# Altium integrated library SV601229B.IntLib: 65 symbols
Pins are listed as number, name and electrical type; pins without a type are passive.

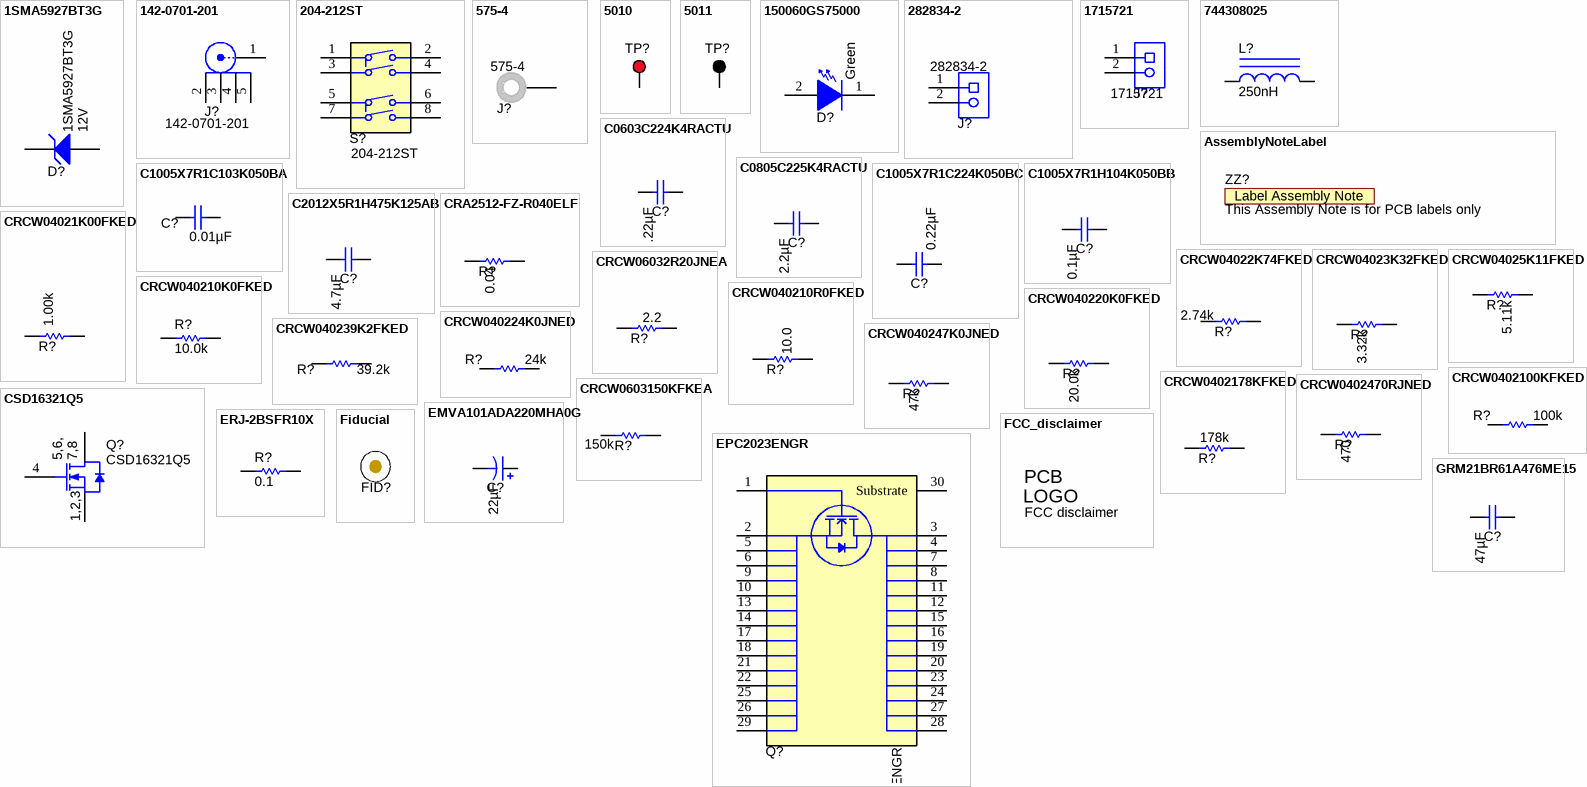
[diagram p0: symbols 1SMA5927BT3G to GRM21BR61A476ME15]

## 1SMA5927BT3G
designator D?  value 12V
Diode, Zener, 12 V, 1.5 W, SMA; Manufacturer: ON Semiconductor; SymbolCreator: a0412235; U/M: EA; Power_W: 1.5; Vz_V: 12; Value1: 1.5W; RJA_CperW: 250
signal-integrity model Diode
footprint SMA
pins: 1 K, 2 A

## 142-0701-201
designator J?
Connector, TH, SMA; Manufacturer: Emerson Network Power; SymbolCreator: X0208326; U/M: EA
footprint Johnson_142-0701-20x
pins: 1, 2, 3, 4, 5

## 204-212ST
designator S?
Switch, DPST, 2 Pos, 0.1 A, 50 VDC, SMD; Manufacturer: CTS Electrocomponents; SymbolCreator: Altium; VDC_V: 50; SwitchFunction: Off-On; PositionCount: 2; CurrentRating_mA: 100
footprint SW_204-212
pins: 1, 2, 3, 4, 5, 6, 7, 8

## 575-4
designator J?
Standard Banana Jack, Uninsulated, 5.5mm; Manufacturer: Keystone; CompType: Connector; U/M: EA
footprint Keystone_575-4
pins: 1

## 5010
designator TP?  (value not drawn)
Test Point, Multipurpose, Red, TH; Manufacturer: Keystone; CompType: Test Point Loop; U/M: EA
footprint Keystone5010
pins: 1

## 5011
designator TP?  (value not drawn)
Test Point, Multipurpose, Black, TH; Manufacturer: Keystone; CompType: Test Point Loop; U/M: EA
footprint Keystone5011
pins: 1

## 150060GS75000
designator D?  value Green  (hidden comment: 150060GS75000)
LED, Green, SMD; Manufacturer: Wurth Elektronik eiSos; Type: InGaN; Vf_V: 3.2; Value2: 3.2V; Io_A: 0.02; Tjmax_C: 85; Value1: W; Angle: 140; U/M: EA
signal-integrity model Diode
footprint WL-SMCW_GREEN
pins: 1 K, 2 A

## 282834-2
designator J?
Terminal Block, 2x1, 2.54mm, TH; Manufacturer: TE Connectivity; SymbolCreator: a0412235; U/M: EA
footprint TEC_282834-2
pins: 1, 2

## 1715721
designator J?
Terminal Block, 5.08 mm, 2x1, TH; Manufacturer: Phoenix Contact; SymbolCreator: a0412235; Pitch_mm: 5.08; Gender: Female; Row_Count: 1; ContactFinish: Tin; Current_A: 17.5; Voltage_V: 400; Cert_CSA: Y; Cert_CULUS: N
footprint PhoenixContact_1715721
pins: 1, 2

## 744308025
designator L?  ValueDisplayed: 250nH  (hidden comment: 744308025)
Inductor, Shielded Drum Core, Ferrite, 250 nH, 27 A, 0.00037 ohm, SMD; Manufacturer: Wurth Elektronik; Value: 250nH; Ind_H: 250.0E-9; Imax_A: 27; Irms: 27A @ 50C rise; Isat: 44A @ 20% inductance drop; Value2: 27A
signal-integrity model Inductor
simulation model Inductor
footprint WE-HCM_1070
pins: 1, 2

## AssemblyNoteLabel
designator ZZ?, comment This Assembly Note is for PCB labels only  (no BOM)
SymbolCreator: a0412235
footprint AssemblyNoteLabel

## C0603C224K4RACTU
designator C?  ValueDisplayed: 0.22µF  (hidden comment: C0603C224K4RACTU)
CAP, CERM, 0.22 µF, 16 V, +/- 10%, X7R, 0603; Manufacturer: Kemet; Polarized: N; CompType: Capacitor; Value: 0.22uF; U/M: EA; Cap_F: 0.00000022; Tolerance_%: 10; Value1: Unknown; VDC_V: 16; Value2: 16V; TaMin_C: -55; TaMax_C: 125; Cap_Case: 0603
signal-integrity model Cap
simulation model Cap
footprint 0603
footprint 0603M
footprint 0603L
footprint 0603_HV
footprint 0603S
pins: 1, 2

## C0805C225K4RACTU
designator C?  ValueDisplayed: 2.2µF  (hidden comment: C0805C225K4RACTU)
CAP, CERM, 2.2 µF, 16 V, +/- 10%, X7R, 0805; Manufacturer: Kemet; Polarized: N; CompType: Capacitor; Value: 2.2uF; U/M: EA; Cap_F: 0.0000022; Tolerance_%: 10; ESR_ohm: 0.008; Value1: 0.008 ohm; VDC_V: 16; Value2: 16V; IRMS_A: 15.55; TaMin_C: -55; TaMax_C: 125; Cap_Case: 0805
signal-integrity model Cap
simulation model Cap
footprint 0805_HV
footprint 0805
footprint 0805M
footprint 0805L
pins: 1, 2

## C1005X7R1C103K050BA
designator C?  ValueDisplayed: 0.01µF  (hidden comment: C1005X7R1C103K050BA)
CAP, CERM, 0.01 µF, 16 V, +/- 10%, X7R, 0402; Manufacturer: TDK; Polarized: N; CompType: Capacitor; Value: 0.01uF; U/M: EA; Cap_F: 0.00000001; Tolerance_%: 10; ESR_ohm: 0.0623; Value1: 0.0623 ohm; VDC_V: 16; Value2: 16V; TaMin_C: -55; TaMax_C: 125; Cap_Case: 0402; AEC Category: Q200
signal-integrity model Cap
simulation model Cap
footprint 0402
footprint 0402M
footprint 0402L
footprint 0402S
pins: 1, 2

## C1005X7R1C224K050BC
designator C?  ValueDisplayed: 0.22µF  (hidden comment: C1005X7R1C224K050BC)
CAP, CERM, 0.22 µF, 16 V, +/- 10%, X7R, 0402; Manufacturer: TDK; Polarized: N; CompType: Capacitor; Value: 0.22uF; U/M: EA; Cap_F: 0.00000022; Tolerance_%: 10; Value1: Unknown; VDC_V: 16; Value2: 16V; TaMin_C: -55; TaMax_C: 125; Cap_Case: 0402
signal-integrity model Cap
simulation model Cap
footprint 0402
footprint 0402M
footprint 0402L
footprint 0402S
pins: 1, 2

## C1005X7R1H104K050BB
designator C?  ValueDisplayed: 0.1µF  (hidden comment: C1005X7R1H104K050BB)
CAP, CERM, 0.1 µF, 50 V, +/- 10%, X7R, 0402; Manufacturer: TDK; Polarized: N; CompType: Capacitor; Value: 0.1uF; U/M: EA; Cap_F: 0.0000001; Tolerance_%: 10; ESR_ohm: 0.039064; Value1: 0.039064 ohm; VDC_V: 50; Value2: 50V; IRMS_A: 0.814669; TaMin_C: -55; TaMax_C: 125; Cap_Case: 0402; AEC Category: Q200
signal-integrity model Cap
simulation model Cap
footprint 0402
footprint 0402M
footprint 0402L
footprint 0402S
pins: 1, 2

## C2012X5R1H475K125AB
designator C?  ValueDisplayed: 4.7µF  (hidden comment: C2012X5R1H475K125AB)
CAP, CERM, 4.7uF, 50V, +/-10%, X5R, 0805; Manufacturer: TDK; Polarized: N; CompType: Capacitor; U/M: EA; Cap_F: 0.0000047; Tolerance_%: 10; Value1: Unknown; VDC_V: 50; TaMin_C: -55; TaMax_C: 85; Cap_Case: 0805
signal-integrity model Cap
simulation model Cap
footprint 0805_HV
footprint 0805
footprint 0805M
footprint 0805L
pins: 1, 2

## CRA2512-FZ-R040ELF
designator R?  ValueDisplayed: 0.04  (hidden comment: CRA2512-FZ-R040ELF)
RES, 0.04, 1%, 3 W, 2512; Manufacturer: Bourns; CompType: Resistor; Value: 0.04; Value_Code: R040; Tolerance_%: 1; Power_W: 3; Value2: 3W; VDC_V: 0; TempCo: 75 ppm/C; U/M: EA
signal-integrity model Resistor
simulation model Resistor
footprint 2512
footprint 2512M
footprint 2512L
pins: 1, 2

## CRCW04021K00FKED
designator R?  ValueDisplayed: 1.00k  (hidden comment: CRCW04021K00FKED)
RES, 1.00 k, 1%, 0.063 W, 0402; Manufacturer: Vishay-Dale; CompType: Resistor; Value: 1.00k; Res_ohm: 1000; Value_Code: 1k00; Tolerance_%: 1; Power_W: 0.063; Value2: 0.063W; VDC_V: 50; TempCo: 100 ppm/C; EIA_Code: E96; U/M: EA; AEC Category: Q200
signal-integrity model Resistor
simulation model Resistor
footprint 0402
footprint 0402M
footprint 0402L
footprint 0402S
pins: 1, 2

## CRCW04022K74FKED
designator R?  ValueDisplayed: 2.74k  (hidden comment: CRCW04022K74FKED)
RES, 2.74 k, 1%, 0.063 W, 0402; Manufacturer: Vishay-Dale; CompType: Resistor; Value: 2.74k; Res_ohm: 2740; Value_Code: 2k74; Tolerance_%: 1; Power_W: 0.063; Value2: 0.063W; VDC_V: 50; TempCo: 100 ppm/C; EIA_Code: E96; U/M: EA
signal-integrity model Resistor
simulation model Resistor
footprint 0402
footprint 0402M
footprint 0402L
footprint 0402S
pins: 1, 2

## CRCW04023K32FKED
designator R?  ValueDisplayed: 3.32k  (hidden comment: CRCW04023K32FKED)
RES, 3.32 k, 1%, 0.063 W, 0402; Manufacturer: Vishay-Dale; CompType: Resistor; Value: 3.32k; Res_ohm: 3320; Value_Code: 3k32; Tolerance_%: 1; Power_W: 0.063; Value2: 0.063W; VDC_V: 50; TempCo: 100 ppm/C; EIA_Code: E96; U/M: EA
signal-integrity model Resistor
simulation model Resistor
footprint 0402
footprint 0402M
footprint 0402L
footprint 0402S
pins: 1, 2

## CRCW04025K11FKED
designator R?  ValueDisplayed: 5.11k  (hidden comment: CRCW04025K11FKED)
RES, 5.11 k, 1%, 0.063 W, 0402; Manufacturer: Vishay-Dale; CompType: Resistor; Value: 5.11k; Res_ohm: 5110; Value_Code: 5k11; Tolerance_%: 1; Power_W: 0.063; Value2: 0.063W; VDC_V: 50; TempCo: 100 ppm/C; EIA_Code: E96; U/M: EA
signal-integrity model Resistor
simulation model Resistor
footprint 0402
footprint 0402M
footprint 0402L
footprint 0402S
pins: 1, 2

## CRCW06032R20JNEA
designator R?  ValueDisplayed: 2.2  (hidden comment: CRCW06032R20JNEA)
RES, 2.2, 5%, 0.1 W, 0603; Manufacturer: Vishay-Dale; CompType: Resistor; Value: 2.2; Value_Code: 2R20; Tolerance_%: 5; Power_W: 0.1; Value2: 0.1W; VDC_V: 75; TempCo: 200 ppm/C; EIA_Code: E24; U/M: EA
signal-integrity model Resistor
simulation model Resistor
footprint 0603
footprint 0603M
footprint 0603L
footprint 0603_HV
footprint 0603S
pins: 1, 2

## CRCW040210K0FKED
designator R?  ValueDisplayed: 10.0k  (hidden comment: CRCW040210K0FKED)
RES, 10.0 k, 1%, 0.063 W, 0402; Manufacturer: Vishay-Dale; CompType: Resistor; Value: 10.0k; Res_ohm: 10000; Value_Code: 10k0; Tolerance_%: 1; Power_W: 0.063; Value2: 0.063W; VDC_V: 50; TempCo: 100 ppm/C; EIA_Code: E96; U/M: EA
signal-integrity model Resistor
simulation model Resistor
footprint 0402
footprint 0402M
footprint 0402L
footprint 0402S
pins: 1, 2

## CRCW040210R0FKED
designator R?  ValueDisplayed: 10.0  (hidden comment: CRCW040210R0FKED)
RES, 10.0, 1%, 0.063 W, 0402; Manufacturer: Vishay-Dale; CompType: Resistor; Value: 10.0; Res_ohm: 10; Value_Code: 10R0; Tolerance_%: 1; Power_W: 0.063; Value2: 0.063W; VDC_V: 50; TempCo: 100 ppm/C; EIA_Code: E96; U/M: EA
signal-integrity model Resistor
simulation model Resistor
footprint 0402
footprint 0402M
footprint 0402L
footprint 0402S
pins: 1, 2

## CRCW040220K0FKED
designator R?  ValueDisplayed: 20.0k  (hidden comment: CRCW040220K0FKED)
RES, 20.0 k, 1%, 0.063 W, 0402; Manufacturer: Vishay-Dale; CompType: Resistor; Value: 20.0k; Res_ohm: 20000; Value_Code: 20k0; Tolerance_%: 1; Power_W: 0.063; Value2: 0.063W; VDC_V: 50; TempCo: 100 ppm/C; EIA_Code: E96; U/M: EA
signal-integrity model Resistor
simulation model Resistor
footprint 0402
footprint 0402M
footprint 0402L
footprint 0402S
pins: 1, 2

## CRCW040224K0JNED
designator R?  ValueDisplayed: 24k  (hidden comment: CRCW040224K0JNED)
RES, 24 k, 5%, 0.063 W, 0402; Manufacturer: Vishay-Dale; CompType: Resistor; Value: 24k; Res_ohm: 24000; Value_Code: 24k0; Tolerance_%: 5; Power_W: 0.063; Value2: 0.063W; VDC_V: 50; TempCo: 200 ppm/C; EIA_Code: E24; U/M: EA
signal-integrity model Resistor
simulation model Resistor
footprint 0402
footprint 0402M
footprint 0402L
footprint 0402S
pins: 1, 2

## CRCW040239K2FKED
designator R?  ValueDisplayed: 39.2k  (hidden comment: CRCW040239K2FKED)
RES, 39.2 k, 1%, 0.063 W, 0402; Manufacturer: Vishay-Dale; CompType: Resistor; Value: 39.2k; Res_ohm: 39200; Value_Code: 39k2; Tolerance_%: 1; Power_W: 0.063; Value2: 0.063W; VDC_V: 50; TempCo: 100 ppm/C; EIA_Code: E96; U/M: EA
signal-integrity model Resistor
simulation model Resistor
footprint 0402
footprint 0402M
footprint 0402L
footprint 0402S
pins: 1, 2

## CRCW040247K0JNED
designator R?  ValueDisplayed: 47k  (hidden comment: CRCW040247K0JNED)
RES, 47 k, 5%, 0.063 W, 0402; Manufacturer: Vishay-Dale; CompType: Resistor; Value: 47k; Res_ohm: 47000; Value_Code: 47k0; Tolerance_%: 5; Power_W: 0.063; Value2: 0.063W; VDC_V: 50; TempCo: 200 ppm/C; EIA_Code: E24; U/M: EA
signal-integrity model Resistor
simulation model Resistor
footprint 0402
footprint 0402M
footprint 0402L
footprint 0402S
pins: 1, 2

## CRCW0402100KFKED
designator R?  ValueDisplayed: 100k  (hidden comment: CRCW0402100KFKED)
RES, 100 k, 1%, 0.063 W, 0402; Manufacturer: Vishay-Dale; CompType: Resistor; Value: 100k; Res_ohm: 100000; Tolerance_%: 1; Power_W: 0.063; Value2: 0.063W; VDC_V: 50; TempCo: 100 ppm/C; EIA_Code: E96; U/M: EA
signal-integrity model Resistor
simulation model Resistor
footprint 0402
footprint 0402M
footprint 0402L
footprint 0402S
pins: 1, 2

## CRCW0402178KFKED
designator R?  ValueDisplayed: 178k  (hidden comment: CRCW0402178KFKED)
RES, 178 k, 1%, 0.063 W, 0402; Manufacturer: Vishay-Dale; CompType: Resistor; Value: 178k; Res_ohm: 178000; Tolerance_%: 1; Power_W: 0.063; Value2: 0.063W; VDC_V: 50; TempCo: 100 ppm/C; EIA_Code: E96; U/M: EA
signal-integrity model Resistor
simulation model Resistor
footprint 0402
footprint 0402M
footprint 0402L
footprint 0402S
pins: 1, 2

## CRCW0402470RJNED
designator R?  ValueDisplayed: 470  (hidden comment: CRCW0402470RJNED)
RES, 470, 5%, 0.063 W, 0402; Manufacturer: Vishay-Dale; CompType: Resistor; Value: 470; Value_Code: 470R; Tolerance_%: 5; Power_W: 0.063; Value2: 0.063W; VDC_V: 50; TempCo: 200 ppm/C; EIA_Code: E24; U/M: EA
signal-integrity model Resistor
simulation model Resistor
footprint 0402
footprint 0402M
footprint 0402L
footprint 0402S
pins: 1, 2

## CRCW0603150KFKEA
designator R?  ValueDisplayed: 150k  (hidden comment: CRCW0603150KFKEA)
RES, 150 k, 1%, 0.1 W, 0603; Manufacturer: Vishay-Dale; CompType: Resistor; Value: 150k; Res_ohm: 150000; Tolerance_%: 1; Power_W: 0.1; Value2: 0.1W; VDC_V: 75; TempCo: 100 ppm/C; EIA_Code: E96; U/M: EA
signal-integrity model Resistor
simulation model Resistor
footprint 0603
footprint 0603M
footprint 0603L
footprint 0603_HV
footprint 0603S
pins: 1, 2

## CSD16321Q5
designator Q?
MOSFET, N-CH, 25 V, 100 A, SON 5x6mm; Manufacturer: Texas Instruments; Alternate Manufacturer: None; U/M: EA; ChType: N; Value: 25V; VdsMax_V: 25; Value1: 0.0021 ohm; Rdson45_ohm: 0.0021; Value2: 14 nC; QgTyp_nC: 14; Vgs_V: 10; IdsMax_A: 100; AEC Category: Q101
footprint TRANS_NexFET_Q5
simulation model CSD16321Q5
pins: 1 S, 2 S, 3 S, 4 G, 5 D, 6 D, 7 D, 8 D, 9 D

## EMVA101ADA220MHA0G
designator C?  ValueDisplayed: 22µF  (hidden comment: EMVA101ADA220MHA0G)
CAP, AL, 22 µF, 100 V, +/- 20%,  ohm, SMD; Manufacturer: Chemi-Con; Polarized: Y; CompType: Capacitor; Value: 22uF; U/M: EA; Cap_F: 0.000022; Tolerance_%: 20; Value1: Unknown; VDC_V: 100; Value2: 100V; IRMS_A: 0.09; TaMin_C: -40; TaMax_C: 85; Cap_Case: HA0
signal-integrity model Cap
simulation model Cap
footprint CAPSMT_62_HA0
pins: 1 +, 2 -

## EPC2023ENGR
designator Q?
MOSFET, N-CH, 30 V, 60 A, 6.05x2.3mm; Manufacturer: EPC; Alternate Manufacturer: None; SymbolCreator: Altium; U/M: EA; ChType: N; Value: 30V; VdsMax_V: 30; Value1: ? ohm; Value2: 20 nC; QgTyp_nC: 20; Vgs_V: 6; IdsMax_A: 60; AEC Category: Q101
footprint EPC2023
pins: 1 G, 2 S, 3 D, 4 D, 5 S, 6 S, 7 D, 8 D, 9 S, 10 S, 11 D, 12 D, 13 S, 14 S, 15 D, 16 D, 17 S, 18 S, 19 D, 20 D, 21 S, 22 S, 23 D, 24 D, 25 S, 26 S, 27 D, 28 D, 29 S, 30 Substrate

## ERJ-2BSFR10X
designator R?  ValueDisplayed: 0.1  (hidden comment: ERJ-2BSFR10X)
RES, 0.1, 1%, 0.125 W, 0402; Manufacturer: Panasonic; CompType: Resistor; Value: 0.1; Value_Code: R100; Tolerance_%: 1; Power_W: 0.125; Value2: 0.125W; TempCo: 300 ppm/C; EIA_Code: E96; U/M: EA
signal-integrity model Resistor
simulation model Resistor
footprint 0402
footprint 0402M
footprint 0402L
footprint 0402S
pins: 1, 2

## FCC_disclaimer
designator Logo?, comment FCC disclaimer  (no BOM)
FCC_disclaimer; SymbolCreator: codlsc
footprint FCC_disclaimer
footprint FCC_disclaimer_stacked

## Fiducial
designator FID?  (value not drawn)  (mechanical)
Fiducial mark.  There is nothing to buy or mount.; SymbolCreator: codlsc
footprint Fiducial10-30
footprint Fiducial10-20
footprint Fiducial15-30
footprint Fiducial20-40
footprint Fiducial6.4-20

## GRM21BR61A476ME15
designator C?  ValueDisplayed: 47µF  (hidden comment: GRM21BR61A476ME15)
CAP, CERM, 47 µF, 10 V, +/- 20%, X5R, 0805; Manufacturer: MuRata; Polarized: N; CompType: Capacitor; Value: 47uF; U/M: EA; Cap_F: 0.000047; Tolerance_%: 20; Value1: Unknown; VDC_V: 10; Value2: 10V; TaMin_C: -55; TaMax_C: 85; Cap_Case: 0805; AEC Category: Q200
signal-integrity model Cap
simulation model Cap
footprint 0805_HV
footprint 0805_HV1
footprint 0805
footprint 0805M
footprint 0805L
pins: 1, 2

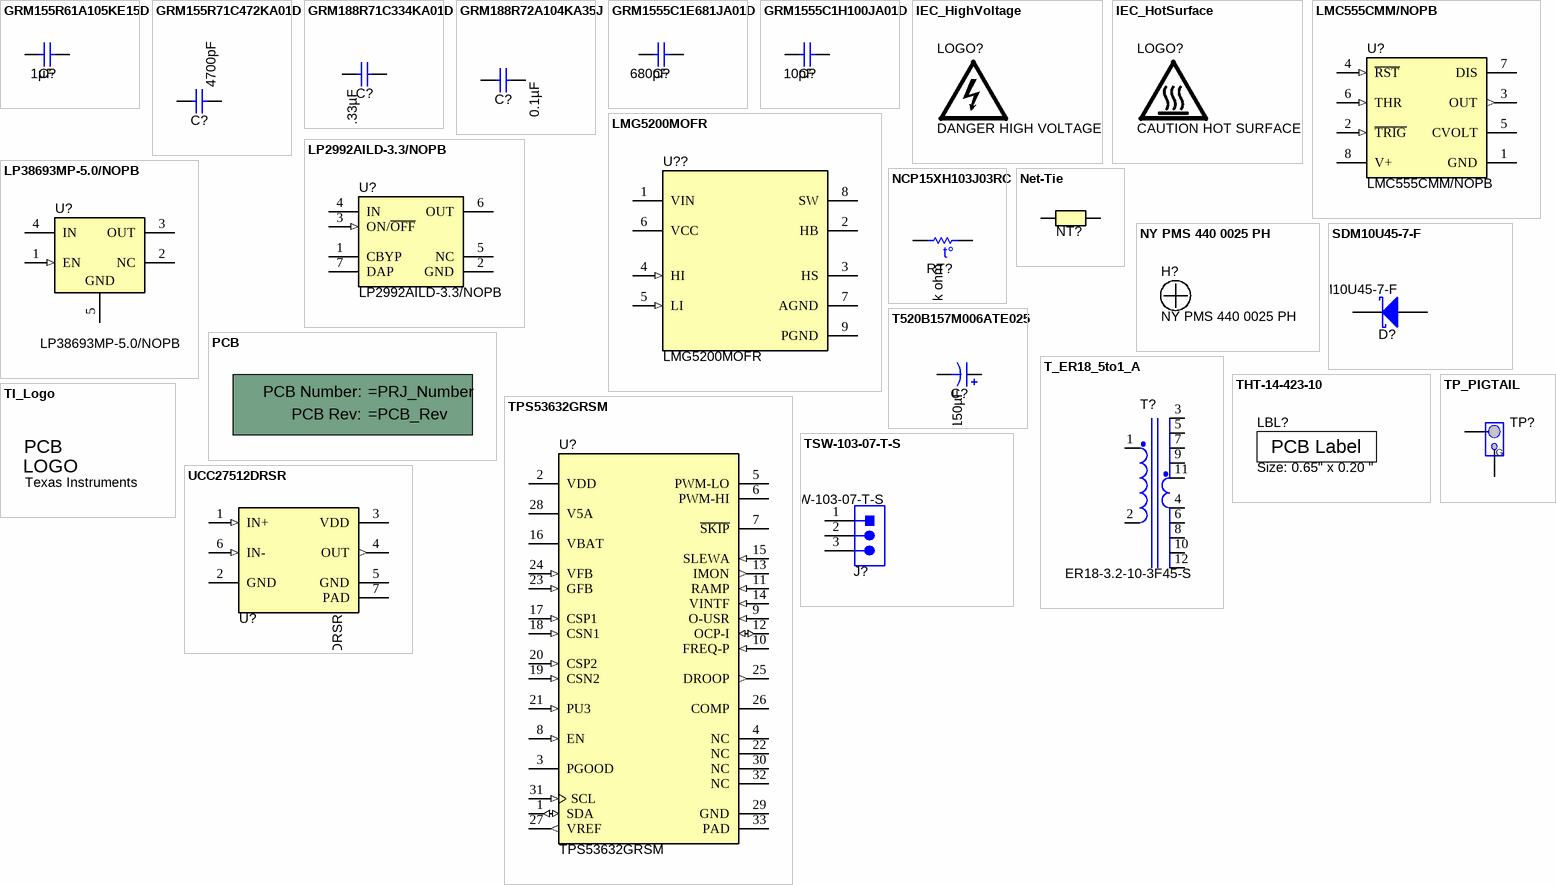
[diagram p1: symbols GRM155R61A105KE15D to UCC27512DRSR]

## GRM155R61A105KE15D
designator C?  ValueDisplayed: 1µF  (hidden comment: GRM155R61A105KE15D)
CAP, CERM, 1uF, 10V, +/-10%, X5R, 0402; Manufacturer: MuRata; Polarized: N; CompType: Capacitor; U/M: EA; Cap_F: 0.000001; Tolerance_%: 10; Value1: Unknown; TaMin_C: -55; TaMax_C: 85; Cap_Case: 0402
signal-integrity model Cap
simulation model Cap
footprint 0402
footprint 0402M
footprint 0402L
footprint 0402S
pins: 1, 2

## GRM155R71C472KA01D
designator C?  ValueDisplayed: 4700pF  (hidden comment: GRM155R71C472KA01D)
CAP, CERM, 4700 pF, 16 V, +/- 10%, X7R, 0402; Manufacturer: MuRata; Polarized: N; CompType: Capacitor; Value: 4700pF; U/M: EA; Cap_F: 0.0000000047; Tolerance_%: 10; Value1: Unknown; VDC_V: 16; Value2: 16V; TaMin_C: -55; TaMax_C: 125; Cap_Case: 0402; AEC Category: Q200
signal-integrity model Cap
simulation model Cap
footprint 0402
footprint 0402M
footprint 0402L
footprint 0402S
pins: 1, 2

## GRM188R71C334KA01D
designator C?  ValueDisplayed: 0.33µF  (hidden comment: GRM188R71C334KA01D)
CAP, CERM, 0.33 µF, 16 V, +/- 10%, X7R, 0603; Manufacturer: MuRata; Polarized: N; CompType: Capacitor; Value: 0.33uF; U/M: EA; Cap_F: 0.00000033; Tolerance_%: 10; Value1: Unknown; VDC_V: 16; Value2: 16V; TaMin_C: -55; TaMax_C: 125; Cap_Case: 0603
signal-integrity model Cap
simulation model Cap
footprint 0603
footprint 0603M
footprint 0603L
footprint 0603_HV
footprint 0603S
pins: 1, 2

## GRM188R72A104KA35J
designator C?  ValueDisplayed: 0.1µF  (hidden comment: GRM188R72A104KA35J)
CAP, CERM, 0.1uF, 100V, +/-10%, X7R, 0603; Manufacturer: MuRata; Polarized: N; CompType: Capacitor; U/M: EA; Cap_F: 0.0000001; Tolerance_%: 10; Value1: Unknown; VDC_V: 100; TaMin_C: -55; TaMax_C: 125; Cap_Case: 0603
signal-integrity model Cap
simulation model Cap
footprint 0603
footprint 0603M
footprint 0603L
footprint 0603_HV
footprint 0603S
pins: 1, 2

## GRM1555C1E681JA01D
designator C?  ValueDisplayed: 680pF  (hidden comment: GRM1555C1E681JA01D)
CAP, CERM, 680 pF, 25 V, +/- 5%, C0G/NP0, 0402; Manufacturer: MuRata; Polarized: N; CompType: Capacitor; Value: 680pF; U/M: EA; Cap_F: 0.00000000068; Tolerance_%: 5; Value1: Unknown; VDC_V: 25; Value2: 25V; TaMin_C: -55; TaMax_C: 125; Cap_Case: 0402
signal-integrity model Cap
simulation model Cap
footprint 0402
footprint 0402M
footprint 0402L
footprint 0402S
pins: 1, 2

## GRM1555C1H100JA01D
designator C?  ValueDisplayed: 10pF  (hidden comment: GRM1555C1H100JA01D)
CAP, CERM, 10 pF, 50 V, +/- 5%, C0G/NP0, 0402; Manufacturer: MuRata; Polarized: N; CompType: Capacitor; Value: 10pF; U/M: EA; Cap_F: 0.00000000001; Tolerance_%: 5; Value1: Unknown; VDC_V: 50; Value2: 50V; TaMin_C: -55; TaMax_C: 125; Cap_Case: 0402
signal-integrity model Cap
simulation model Cap
footprint 0402
footprint 0402M
footprint 0402L
footprint 0402S
pins: 1, 2

## IEC_HighVoltage
designator LOGO?, comment DANGER HIGH VOLTAGE  (no BOM)
IEC 61010-1 High Voltage Warning; SymbolCreator: a0412235
footprint IEC_HighVoltage_Large
footprint IEC_HighVoltage_Medium
footprint IEC_HighVoltage_Small

## IEC_HotSurface
designator LOGO?, comment CAUTION HOT SURFACE  (no BOM)
IEC 61010-1 Hot Surface Warning; SymbolCreator: a0412235
footprint IEC_HotSurface_Large
footprint IEC_HotSurface_Medium
footprint IEC_HotSurface_Small

## LMC555CMM/NOPB
designator U?
CMOS Timer, 8-pin Mini SOIC, Pb-Free; Manufacturer: Texas Instruments; PackageTopMarking: ZXTT*ZC5; PowerWise: N; CompType: Analog IC
footprint MUA08A_N (TSOP, 8-Leads, Body 3x3mm, Pitch 0.65mm, IPC Medium Density)
footprint MUA08A_L (TSOP, 8-Leads, Body 3x3mm, Pitch 0.65mm, IPC High Density)
footprint MUA08A_M (TSOP, 8-Leads, Body 3x3mm, Pitch 0.65mm, IPC Low Density)
pins: 1 GND (power), 2 ~{TRIG} (in), 3 OUT (out), 4 ~{RST} (in), 5 CVOLT, 6 THR (in), 7 DIS (oc), 8 V+ (power)

## LMG5200MOFR
designator U??
80V, 10A GaN Half-Bridge Power Stage, MOF0009A (QFM-9); Alternate PartNumber: LMG5200MOFT; Manufacturer: Texas Instruments; SymbolCreator: Altium; SizeArea_mm2: 48; SizeAreaWB_mm2: 80; SizeX_mm: 6; SizeY_mm: 8; SizeZ_mm: 2; CompType: IC; U/M: EA
footprint MOF0009A
pins: 1 VIN (power) "Input voltage pin. Electrically connected to high-side GaN FET drain.", 2 HB (power) "High-side gate driver bootstrap rail.", 3 HS (power) "High-side GaN FET source connection", 4 HI (in) "High-side driver control Input", 5 LI (in) "Low-side driver control input", 6 VCC (power) "5V positive gate drive supply", 7 AGND (power) "Analog Ground. Ground of driver IC.", 8 SW (power) "Switching node. Low-side GaN FET drain. Electrically shorted to HS pin.", 9 PGND (power) "Power Ground. Low-side GaN FET source. Electrically shorted to AGND pin."
1 alternate drawing of the same symbol

## LP2992AILD-3.3/NOPB
designator U?
Micropower 250 mA Low-Noise Ultra Low-Dropout Regulator, 6-pin LLP, Pb-Free; Manufacturer: Texas Instruments; PackageTopMarking: ZXYTT*L014A; PowerWise: N; CompType: LDO IC
footprint LDE06A (PSON, 6-Leads, Body 2.92x3.29 mm, Pitch 0.95mm, NSC Recommended)
pins: 1 CBYP, 2 GND (power), 3 ON/~{OFF} (in), 4 IN (power), 5 NC, 6 OUT (power), 7 DAP (power)

## LP38693MP-5.0/NOPB
designator U?
500mA Low Dropout CMOS Linear Regulators Stable with Ceramic Output Capacitors, 5-pin SOT-223, Pb-Free; Manufacturer: Texas Instruments; PackageTopMarking: XYTT*LJZB; PowerWise: Y; CompType: LDO IC
footprint MP05A_N (SOT223, 5-Leads, Body 6.5x3.5mm, Pitch 1.5mm, Lead Span 7mm, IPC Medium Density)
footprint MP05A_L (SOT223, 5-Leads, Body 6.5x3.5mm, Pitch 1.5mm, Lead Span 7mm, IPC High Density)
footprint MP05A_M (SOT223, 5-Leads, Body 6.5x3.5mm, Pitch 1.5mm, Lead Span 7mm, IPC Low Density)
pins: 1 EN (in), 2 NC, 3 OUT (power), 4 IN (power), 5 GND (power)

## NCP15XH103J03RC
designator RT?  value 10k ohm  (hidden comment: NCP15XH103J03RC)
Thermistor NTC, 10k ohm, 5%, 0402; Manufacturer: MuRata; Tolerance_%: 5; Power_W: 0.1; TaMin_C: -40; TaMax_C: 125; U/M: EA
footprint 0402
footprint 0402M
footprint 0402L
footprint 0402S
pins: 1, 2

## Net-Tie
designator NT?, comment Net-tie connecting GND polygons under signal traces  (value not drawn)  (net tie, no BOM)
Single point connection between nets.; SymbolCreator: codlsc
footprint Net-Tie_10mil (10mil net tie, no solder mask opening, no solder paste)
footprint NetTie_1206 (1206 pads tied by 10mil copper trace which can be cut.  Part can be placed on pads.)
footprint Net-Tie_0805_HV
footprint NetTie_1206_NoOverlay (1206 pads tied by 10mil copper trace which can be cut.  Part can be placed on pads.)
footprint Net-Tie_0805_HV_NoOverlay (0805_HV pads tied by 10mil copper trace which can be cut.  An 0805 part can be placed on pads.)
footprint Net-Tie_10milWide_30milLong
footprint Net-Tie_20milWide_60milLong
footprint NetTie_0603
footprint NetTie_0402
footprint Net-Tie_50milWide_30milLong
pins: 1, 2

## NY PMS 440 0025 PH
designator H?
Machine Screw, Round, #4-40 x 1/4, Nylon, Philips panhead; Manufacturer: B&F Fastener Supply; CompType: Hardware; SymbolCreator: codlsc; U/M: EA
footprint NY PMS 440 0025 PH
footprint NY PMS 440 0025 PH_3Donly

## PCB
designator !PCB?, comment Printed Circuit Board  (value not drawn)  (mechanical)
Manufacturer: Any; SymbolCreator: a0412235; CompType: PCB
1 alternate drawing of the same symbol

## SDM10U45-7-F
designator D?
Diode, Schottky, 45 V, 0.1 A, SOD-523; Manufacturer: Diodes Inc.; U/M: EA; Vf_V: 0.58; Value: 45V; Value1: 0.1A; Value2: 0.58V; Io_A: 0.1; Vr_V: 45; TJmax_C: 125; AEC Category: Q101
signal-integrity model Diode
simulation model DI_SDM10U45
footprint SOD-523
pins: 1 K, 2 A

## T520B157M006ATE025
designator C?  ValueDisplayed: 150µF  (hidden comment: T520B157M006ATE025)
CAP, TA, 150 µF, 6.3 V, +/- 20%, 0.025 ohm, SMD; Manufacturer: Kemet; Polarized: Y; CompType: Capacitor; Value: 150uF; U/M: EA; Cap_F: 0.00015; Tolerance_%: 20; VDC_V: 6.3; Value2: 6.3V; ESR_ohm: 0.025; IRMS_A: 2.3; TaMin_C: -55; TaMax_C: 105; Cap_Case: 3528-21; AEC Category: Q200; AEC Qualified: N
signal-integrity model Cap
simulation model Cap
footprint 3528-21
pins: 1 +, 2 -

## T_ER18_5to1_A
designator T?, comment ER18-3.2-10-3F45-S  (net tie)
Transformer ER18 5:1 turns ratio; Manufacturer: Ferroxcube; SymbolVersion: use current date i.e. 2008-05-20; SymbolCreator: a0220741; U/M: EA
footprint ER18_5to1_A (ER18 transformer, 5:1 ratio)
footprint ER18_3to1_A
pins: 1, 2, 3, 4, 5, 6, 7, 8, 9, 10, 11, 12

## THT-14-423-10
designator LBL?, comment Size: 0.65" x 0.20 "
Thermal Transfer Printable Labels, 0.650" W x 0.200" H - 10,000 per roll; Manufacturer: Brady; PartNumber: THT-14-423-10; SymbolCreator: a0412235; CompType: Label
footprint Label_650x200

## TI_Logo
designator Logo?, comment Texas Instruments  (no BOM)
Texas Instrument Corporate Signature; SymbolCreator: a0412235
footprint TI_Stacked_SolderMask_Medium
footprint TI_Stacked_SolderMask_Medium_Vertical
footprint TI_Stacked_SolderMask_Small
footprint TI_Stacked_SolderMask_Small_Vertical
footprint TI_Stacked_Overlay_Medium
footprint TI_Stacked_Overlay_Medium_Vertical
footprint TI_Stacked_Overlay_Small
footprint TI_Stacked_Overlay_Small_Vertical
footprint TI_Horizontal_SolderMask_Small
footprint TI_Horizontal_Overlay_Medium
footprint TI_Horizontal_Overlay_Small
footprint TI_Symbol_SolderMask_Medium
footprint TI_Symbol_SolderMask_Small
footprint TI_Symbol_Overlay_Medium
footprint TI_Symbol_Overlay_Small
footprint TI_Horizontal_SolderMask_Medium

## TP_PIGTAIL
designator TP?  (value not drawn)  (no BOM)
Testpoint PCB footprint for pigtail probe; Manufacturer: Used in BOM report; SymbolVersion: use current date i.e. 2008-05-20; SymbolCreator: Use a-id; CompType: Used in some BOM reports.  Useful for finding later.; U/M: EA, IN, or GM
footprint TP_PIGTAIL (Scope pigtail footprint)
pins: 1, 2

## TPS53632GRSM
designator U?
Half-Bridge D-CAP+TM Controller for 48V GaN DC/DC Converter, RSM0032B; Manufacturer: Texas Instruments; SymbolCreator: Altium; CompType: IC; U/M: EA
footprint RSM0032B
footprint RSM0032B_NV
pins: 1 SDA (io), 2 VDD (power), 3 PGOOD (oc), 4 NC, 5 PWM-LO (hiz), 6 PWM-HI (hiz), 7 ~{SKIP} (hiz), 8 EN (in), 9 O-USR (in), 10 FREQ-P (in), 11 RAMP (in), 12 OCP-I (io), 13 IMON (out), 14 VINTF (in), 15 SLEWA (in), 16 VBAT (power), 17 CSP1 (in), 18 CSN1 (in), 19 CSN2 (in), 20 CSP2 (in), 21 PU3 (in), 22 NC, 23 GFB (in), 24 VFB (in), 25 DROOP (out), 26 COMP, 27 VREF (out), 28 V5A (power), 29 GND (power), 30 NC, 31 SCL (in), 32 NC, 33 PAD (power)

## TSW-103-07-T-S
designator J?
Header, 2.54 mm, 3x1, Tin, TH; Manufacturer: Samtec; SymbolCreator: a0799628; U/M: EA
footprint Samtec_TSW-103-07-T-S
pins: 1, 2, 3
3 alternate drawings of the same symbol

## UCC27512DRSR
designator U?
Single-Channel High-Speed Low-Side Gate Driver with 4-A Peak Source and 8-A Peak Sink, DRS0006A; Alternate PartNumber: UCC27512DRST; Manufacturer: Texas Instruments; SymbolCreator: a0411947; CompType: IC; U/M: EA
footprint DRS0006A
pins: 1 IN+ (in), 2 GND (power), 3 VDD (power), 4 OUT (out), 5 GND (power), 6 IN- (in), 7 PAD
1 alternate drawing of the same symbol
